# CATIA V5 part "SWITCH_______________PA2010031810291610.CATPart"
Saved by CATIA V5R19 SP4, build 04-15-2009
Part number: SWITCH_______________PA2010031810291610
Bounding box of the stored display mesh (mm): x -7 to 7, y -16.7 to 16.7, z -25.3 to 6.967
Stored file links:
  E:\CadInnWork\InWork\SWITCH_______________PA2010031810291610.CATPart
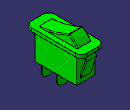
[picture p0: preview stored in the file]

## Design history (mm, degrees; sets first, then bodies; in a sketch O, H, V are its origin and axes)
Parameters
  Update = false
  PDM_version = "A"
  PDM_iteration = 1
  PDM_owner = "moren                    "
  PDM_comment = ""
  PDM_partnumber = "PA002170EA6A57201003181029160010"
Body1 (main body)
  Sketch1 on xy-plane, origin (0, 0, 0), H (1, 0, 0), V (0, 1, 0)
    line L1 (7, 13.2) -> (7, -13.2)
    line L2 (3.5, -16.7) -> (-3.5, -16.7)
    line L3 (-7, -13.2) -> (-7, 13.2)
    line L4 (-3.5, 16.7) -> (3.5, 16.7)
    point P1 (7, 16.7)
    point P2 (7, -16.7)
    point P3 (-7, 16.7)
    arc A1 centre (3.5, 13.2) radius 3.5 from (7, 13.2) to (3.5, 16.7) ccw
    arc A2 centre (-3.5, 13.2) radius 3.5 from (-3.5, 16.7) to (-7, 13.2) ccw
    arc A3 centre (3.5, -13.2) radius 3.5 from (7, -13.2) to (3.5, -16.7) cw
    arc A4 centre (-3.5, -13.2) radius 3.5 from (-3.5, -16.7) to (-7, -13.2) cw
    distance P1 P2 = 33.4
    distance P3 P1 = 14
    radius A1 = 3.5
    radius A2 = 3.5
    radius A3 = 3.5
    radius A4 = 3.5
    vertical: L1 V, L3 V
    horizontal: L2 H, L4 H
    equidistance: L1 L3 O, L2 L4 O
    coincidence: L1 P1, L4 P1, L4 P3, L3 P3, L1 P2, L2 P2
    tangency: A1 L1, A1 L4, A2 L4, A2 L3, A3 L1, A3 L2, A4 L2, A4 L3
  Pad1: profile Sketch1, direction (0, 0, 1), length 2
  Sketch2 on start face of Pad1, origin (0, 0, 0), H (1, 0, 0), V (0, -1, 0)
    line L1 (5.5, 12.5) -> (5.5, -12.5)
    line L2 (5.5, -12.5) -> (-5.5, -12.5)
    line L3 (-5.5, -12.5) -> (-5.5, 12.5)
    line L4 (-5.5, 12.5) -> (5.5, 12.5)
    length L4 = 11
    length L1 = 25
    vertical: L1 V, L3 V
    horizontal: L2 H, L4 H
    equidistance: L1 L3 O, L2 L4 O
  Pad2: profile Sketch2, direction (0, 0, -1), length 16
  Sketch3 on yz-plane, origin (0, 0, 0), H (0, 1, 0), V (0, 0, 1)
    line L1 (14.9583, 0) -> (16.0274, -3.0527)
    point P1 (14.9583, 0)
    line L2 (16.0274, -3.0527) -> (12.5, -13.4489)
    point P3 (12.5, -13.4489)
    reference projected line E1 (12.5, 0) -> (12.5, -16) from edge [face of Pad2 from Sketch2.L1 | face of Pad2 from Sketch2.L2]
    line L3 (14.1636, 0) -> (15.2341, -3.0566)
    point P4 (14.1636, 0)
    line L4 (15.2341, -3.0566) -> (12.5, -11.1147)
    point P6 (12.5, -11.1147)
    reference projected line E2 (12.5, 0) -> (12.5, -16) from edge [face of Pad2 from Sketch2.L1 | face of Pad2 from Sketch2.L2]
    line L5 (14.1636, 0) -> (14.9583, 0)
    line L6 (12.5, -11.1147) -> (12.5, -13.4489)
    distance L3 L1 = 0.75
    distance L4 L2 = 0.75
    coincidence: P1 H, P3 E1, P4 H, P6 E2
    horizontal: L5 H
    vertical: L6 V
  Pad3: profile Sketch3, direction (1, 0, 0), length 3, mirrored extent
  Mirror1: of Pad3, about zx-plane
  Sketch4 on end face of Pad2, origin (0, 0, -16), H (1, 0, 0), V (0, -1, 0)
    line L1 (-2.4148, 10.353) -> (2.4148, 11.647)
    line L2 (2.4148, 11.647) -> (2.4925, 11.3573)
    line L3 (2.4925, 11.3573) -> (-2.3372, 10.0632)
    line L4 (-2.3372, 10.0632) -> (-2.4148, 10.353)
    reference intersected line E1 through (0, 0) direction (1, 0) from zx-plane
    point P5 (0, 11)
    reference intersected line E2 through (0, 0) direction (0, 1) from yz-plane
    distance L1 L3 = 0.3
    length L1 = 5
    angle E1 L3 = 15
    distance H P5 = 11
    perpendicularity: L2 L1
    parallelism: L4 L2
    midpoint: P5 L1
    coincidence: P5 E2
  Pad4: profile Sketch4, direction (0, 0, -1), length 9.3
  Fillet1: radius 2, on edge [face of Pad4 from Sketch4.L4 | end face of Pad4]; edge [face of Pad4 from Sketch4.L2 | end face of Pad4]
  Sketch5 on face of Pad4 from Sketch4.L1, origin (0.1178, -11.0316, -21.9665), H (0.9659, -0.2588, 0), V (0, 0, 1)
    point P1 (-0.1219, 0.6665)
    reference projected line E1 (2.3781, 5.9665) -> (2.3781, -3.3335) from edge [face of Pad4 from Sketch4.L1 | face of Pad4 from Sketch4.L2]
    reference projected line E2 (-2.6219, 5.9665) -> (-2.6219, -3.3335) from edge [face of Pad4 from Sketch4.L4 | face of Pad4 from Sketch4.L1]
    reference projected line E3 (3.3781, -3.3335) -> (-3.6219, -3.3335) from edge [face of Pad4 from Sketch4.L1 | end face of Pad4]
    distance E3 P1 = 4
    equidistance: E1 E2 P1
  Hole1: placed by Sketch5, at (0, -11, -21.3) direction (0.2588, 0.9659, 0), diameter 1, depth 10
  RectPattern1: of Pad4, Fillet1, Hole1, direction 1 instances 2, spacing 9.2, along edge [face of Pad2 from Sketch2.L3 | end face of Pad2]
  Sketch6 on yz-plane, origin (0, 0, 0), H (0, 1, 0), V (0, 0, 1)
    arc A1 centre (-15.7546, 51.8353) radius 50 from (-11.7, 2) to (6.4447, 7.0336) ccw
    point P2 (-11.7, 2)
    point P3 (6.4447, 7.0336)
    arc A2 centre (-0.6288, -5.6115) radius 14.4891 from (6.4447, 7.0336) to (11.7, 2) cw
    point P5 (6.4447, 7.0336)
    point P6 (11.7, 2)
    reference intersected line E1 (-16.7, 2) -> (16.7, 2) from end face of Pad1
    reference intersected line E2 (-16.7, 2) -> (16.7, 2) from end face of Pad1
    reference projected point E3 (-16.7, 2) from edge [face of Pad1 from Sketch1.L2 | end face of Pad1]
    reference projected point E4 (16.7, 2) from edge [face of Pad1 from Sketch1.L4 | end face of Pad1]
    line L1 (11.7, 2) -> (-11.7, 2)
    distance P2 E3 = 5
    distance P6 E4 = 5
    radius A1 = 50
    coincidence: P5 A1, P6 E1, P2 E2, P3 P5
    horizontal: L1 H
  Pad5: profile Sketch6, direction (1, 0, 0), length 4.25, mirrored extent
  Fillet2: radius 0.5, on edge [face of Pad5 from Sketch6.A1 | face of Pad5 from Sketch6.A2]; edge [face of Pad5 from Sketch6.A1 | end face of Pad5]; edge [face of Pad5 from Sketch6.A2 | end face of Pad5]; edge [start face of Pad5 | face of Pad5 from Sketch6.A2]; edge [start face of Pad5 | face of Pad5 from Sketch6.A1]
